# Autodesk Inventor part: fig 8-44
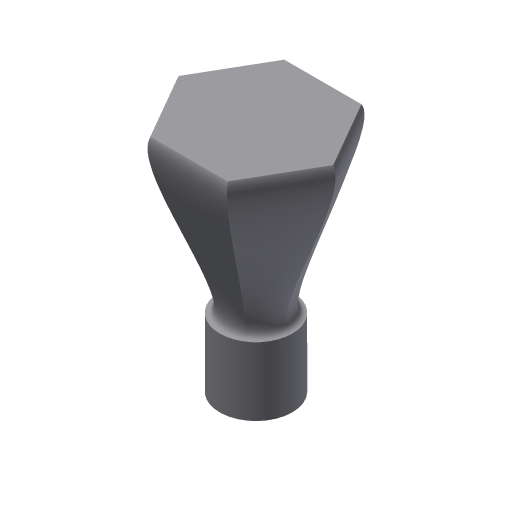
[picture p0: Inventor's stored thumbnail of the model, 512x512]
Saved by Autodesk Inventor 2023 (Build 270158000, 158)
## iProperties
Created: 2004-05
Part Number: fig 8-44
Document SubType Name: Modeling
Designer: CADCIM Technologies
Manufacturer: Standard
Standards Organization: Custom
Density: 1 g/cm^3
Material: Generic
Appearance: Default
Author: CADCIM Technologies
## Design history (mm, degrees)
sketch "Sketch1"
  geometry: C1 r 16.344 at (0, 0)
  constraints: 1 centre point
extrude "Extrusion1" new body sketch "Sketch1" distance "d0" = 30.75; taper "d1" = 0 deg
workplane "Work Plane1"
sketch "Sketch2"
  geometry: L1 (34.788, 0)-(17.394, -30.128); L2 (17.394, -30.128)-(-17.394, -30.128); L3 (-17.394, -30.128)-(-34.788, 0); L4 (-34.788, 0)-(-17.394, 30.128); L5 (-17.394, 30.128)-(17.394, 30.128); L6 (17.394, 30.128)-(34.788, 0); 2 further points
  constraints: 12 end point, 1 coincident, 12 other
loft "Loft2" sketch "Sketch2" dims "d9" = 5, "d10" = 90 deg, "d11" = 40, "d12" = 120 deg
  node "Edges2"
body "Solid1"
other parameters: "d2" = 75
